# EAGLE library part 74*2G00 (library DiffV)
Dual 2-input NAND gate AUC = 3,3 V maximal!
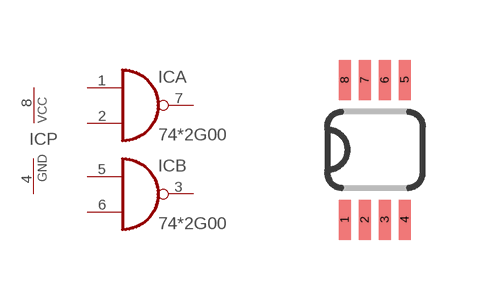
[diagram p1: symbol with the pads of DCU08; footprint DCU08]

Designator prefix IC; gates A=7400 B=7400 P=PWRN

## 74AUC2G00DCU, 74LVC2G00DCU  [DCU08]
1  A:I0  in
2  A:I1  in
3  B:O  out
4  P:GND  pwr
5  B:I0  in
6  B:I1  in
7  A:O  out
8  P:VCC  pwr

## Footprint DCU08 (pad centres in mm)
SMD 8pol. 0,5 mm Texas Instruments
smd 0.3 x 1: 1 -0.75,-1.75; 2 -0.25,-1.75; 3 0.25,-1.75; 4 0.75,-1.75; 5 0.75,1.75; 6 0.25,1.75; 7 -0.25,1.75; 8 -0.75,1.75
